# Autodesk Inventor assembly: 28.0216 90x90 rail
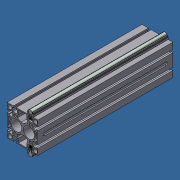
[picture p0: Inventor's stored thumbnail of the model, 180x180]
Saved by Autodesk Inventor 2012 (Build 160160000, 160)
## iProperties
Created: 2011-05
Part Number: 28.0216 90x90 rail
Document SubType Name: Assembly
Designer: Administrator
Author: Administrator
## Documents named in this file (4)
- C:\Andys Backup Data\ANDY'S INVENTOR\INVENTOR LIBRARIES\PARTS LIBRARY\READY FOR USE MODULES LG\SUBCOMPONENTS\28.0216 90x90 rail.iam
- C:\Andys Backup Data\ANDY'S INVENTOR\INVENTOR LIBRARIES\PARTS LIBRARY\READY FOR USE MODULES LG\SUBCOMPONENTS\28.0216_1 90x90S.ipt
- C:\Andys Backup Data\ANDY'S INVENTOR\INVENTOR LIBRARIES\PARTS LIBRARY\READY FOR USE MODULES LG\SUBCOMPONENTS\28.0215_9 SHAFT SUPP PROF.ipt
- C:\Andys Backup Data\ANDY'S INVENTOR\INVENTOR LIBRARIES\PARTS LIBRARY\READY FOR USE MODULES LG\SUBCOMPONENTS\28.0215_8 SHAFT 12.ipt
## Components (5 placed, 3 different names)
1. 28.0216_1 90x90S:1 — Mate:7, Mate:11, Mate:12, Mate:13, Mate:14
2. 28.0215_9 SHAFT SUPP PROF:1 — Mate:2, Mate:4, Mate:10, Mate:13
3. 28.0215_9 SHAFT SUPP PROF:2 — Mate:3, Mate:5, Mate:7, Mate:11
4. 28.0215_8 SHAFT 12:1 — Mate:2, Mate:4, Mate:14
5. 28.0215_8 SHAFT 12:2 — Mate:3, Mate:5, Mate:12
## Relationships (10: Mate 10)
- Mate:2: 28.0215_9 SHAFT SUPP PROF:1 ↔ 28.0215_8 SHAFT 12:1
- Mate:3: 28.0215_9 SHAFT SUPP PROF:2 ↔ 28.0215_8 SHAFT 12:2
- Mate:4: 28.0215_9 SHAFT SUPP PROF:1 ↔ 28.0215_8 SHAFT 12:1
- Mate:5: 28.0215_9 SHAFT SUPP PROF:2 ↔ 28.0215_8 SHAFT 12:2
- Mate:7: 28.0216_1 90x90S:1 ↔ 28.0215_9 SHAFT SUPP PROF:2
- Mate:10: 28.0215_9 SHAFT SUPP PROF:1
- Mate:11: 28.0216_1 90x90S:1 ↔ 28.0215_9 SHAFT SUPP PROF:2
- Mate:12: 28.0216_1 90x90S:1 ↔ 28.0215_8 SHAFT 12:2
- Mate:13: 28.0216_1 90x90S:1 ↔ 28.0215_9 SHAFT SUPP PROF:1
- Mate:14: 28.0216_1 90x90S:1 ↔ 28.0215_8 SHAFT 12:1
